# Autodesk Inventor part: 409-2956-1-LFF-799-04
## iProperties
Created: 2010-11
Part Number: 409-2956-1-LFF-799-04
Material: 3/4" OD TUBE - SS
Document SubType Name: Modeling
Designer: S. Boerckel
Engineer: Steve Boerckel
Mass: 731.966 g
Surface Area: 1099.2 cm^2
Volume: 90.5898 cm^3
Density: 8.08 g/cm^3
Description: DRAIN TUBING
Length: 39.702 in
Author: S. Boerckel
Revision Number: 0
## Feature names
1. Sweep2
